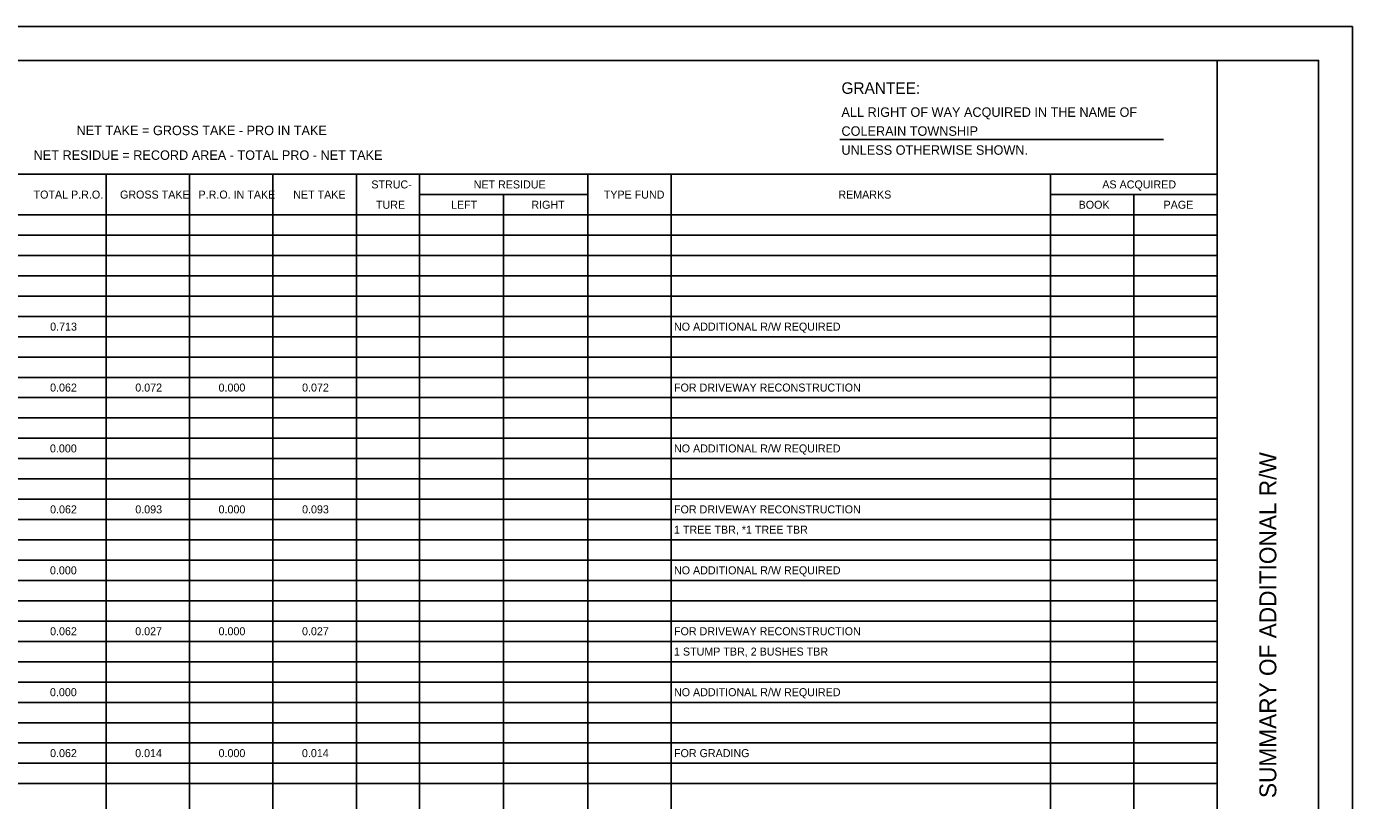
# Model space of a CAD drawing. Extents: x 0 to 34, y 0 to 22.
# Drawn here: x 14.41 to 34, y 10.57 to 22 of the extents above; entities that cross this region are included whole.
import ezdxf

# ---------------------------------------------------------------- set-up
doc = ezdxf.new("R2010")
doc.units = 0
for name, color, linetype in [('Default', 7, 'Continuous'), ('SH_Border', 7, 'Continuous'), ('SH_Cut_Line', 7, 'Continuous'), ('SH_Data', 7, 'Continuous'), ('SH_Text', 7, 'Continuous')]:
    doc.layers.add(name, color=color, linetype=linetype)

msp = doc.modelspace()

# ---------------------------------------------------------------- linework, layer by layer
at = {"layer": 'Default'}
for p, q in [((1.5, 19.818), (32, 19.818)), ((15.587, 19.818), (15.587, 3.02)), ((16.819, 19.818), (16.819, 3.02)), ((18.051, 19.818), (18.051, 3.02)), ((19.283, 19.818), (19.283, 3.02)), ((20.216, 19.818), (20.216, 3.02)), ((22.701, 19.818), (22.701, 3.02)), ((23.933, 19.818), (23.933, 3.02)), ((29.536, 19.818), (29.536, 3.02)), ((32, 19.818), (32, 3.02)), ((20.216, 19.518), (22.701, 19.518)), ((21.458, 19.518), (21.458, 3.02)), ((29.536, 19.518), (32, 19.518)), ((30.768, 19.518), (30.768, 3.02)), ((1.5, 19.218), (32, 19.218)), ((1.5, 18.918), (32, 18.918)), ((1.5, 18.618), (32, 18.618)), ((1.5, 18.318), (32, 18.318)), ((1.5, 18.018), (32, 18.018)), ((1.5, 17.718), (32, 17.718)), ((1.5, 17.418), (32, 17.418)), ((1.5, 17.119), (32, 17.119)), ((1.5, 16.819), (32, 16.819)), ((1.5, 16.519), (32, 16.519)), ((1.5, 16.219), (32, 16.219)), ((1.5, 15.919), (32, 15.919)), ((1.5, 15.619), (32, 15.619)), ((1.5, 15.319), (32, 15.319)), ((1.5, 15.019), (32, 15.019)), ((1.5, 14.719), (32, 14.719)), ((1.5, 14.419), (32, 14.419)), ((1.5, 14.119), (32, 14.119)), ((1.5, 13.819), (32, 13.819)), ((1.5, 13.519), (32, 13.519)), ((1.5, 13.219), (32, 13.219)), ((1.5, 12.919), (32, 12.919)), ((1.5, 12.619), (32, 12.619)), ((1.5, 12.319), (32, 12.319)), ((1.5, 12.019), (32, 12.019)), ((1.5, 11.719), (32, 11.719)), ((1.5, 11.419), (32, 11.419)), ((1.5, 11.119), (32, 11.119)), ((1.5, 10.819), (32, 10.819))]:
    msp.add_line(p, q, dxfattribs=at)
at = {"layer": 'SH_Border'}
msp.add_line((32, 0.5), (32, 21.5), dxfattribs=at)
msp.add_lwpolyline([(1.5, 21.5), (33.5, 21.5), (33.5, 0.5), (1.5, 0.5)], close=True, dxfattribs=at)
at = {"layer": 'SH_Cut_Line'}
msp.add_lwpolyline([(0, 0), (34, 0), (34, 22), (0, 22)], close=True, dxfattribs=at)
at = {"layer": 'SH_Text'}
msp.add_line((26.428, 20.33), (31.208, 20.33), dxfattribs=at)

# ---------------------------------------------------------------- texts
at = {"layer": 'Default'}
for s, height, p in [('STRUC-', 0.1183, (19.504, 19.609)), ('NET RESIDUE', 0.11827, (21.016, 19.609)), ('AS ACQUIRED', 0.11827, (30.304, 19.609)), ('TOTAL P.R.O.', 0.11827, (14.514, 19.459)), ('GROSS TAKE', 0.1183, (15.791, 19.459)), ('P.R.O. IN TAKE', 0.11827, (16.951, 19.459)), ('NET TAKE', 0.1183, (18.35, 19.459)), ('TURE', 0.1183, (19.573, 19.309)), ('LEFT', 0.1183, (20.682, 19.309)), ('RIGHT', 0.1183, (21.868, 19.309)), ('TYPE FUND', 0.1183, (22.938, 19.459)), ('REMARKS', 0.1183, (26.404, 19.459)), ('BOOK', 0.1183, (29.954, 19.309)), ('PAGE', 0.1183, (31.209, 19.309)), ('NO ADDITIONAL R/W REQUIRED', 0.11827, (23.976, 17.509)), ('0.713', 0.1183, (14.759, 17.509)), ('0.062', 0.1183, (14.758, 16.609)), ('0.072', 0.1183, (16.017, 16.609)), ('0.000', 0.1183, (17.247, 16.609)), ('0.072', 0.1183, (18.481, 16.609)), ('FOR DRIVEWAY RECONSTRUCTION', 0.11827, (23.976, 16.609)), ('0.000', 0.1183, (14.756, 15.71)), ('NO ADDITIONAL R/W REQUIRED', 0.11827, (23.976, 15.71)), ('0.062', 0.1183, (14.758, 14.81)), ('0.093', 0.1183, (16.017, 14.81)), ('0.000', 0.1183, (17.247, 14.81)), ('0.093', 0.1183, (18.481, 14.81)), ('FOR DRIVEWAY RECONSTRUCTION', 0.11827, (23.976, 14.81)), ('1 TREE TBR, *1 TREE TBR', 0.11827, (23.976, 14.51)), ('0.000', 0.1183, (14.756, 13.91)), ('NO ADDITIONAL R/W REQUIRED', 0.11827, (23.976, 13.91)), ('0.062', 0.1183, (14.758, 13.01)), ('0.027', 0.1183, (16.016, 13.01)), ('0.000', 0.1183, (17.247, 13.01)), ('0.027', 0.1183, (18.48, 13.01)), ('FOR DRIVEWAY RECONSTRUCTION', 0.11827, (23.976, 13.01)), ('1 STUMP TBR, 2 BUSHES TBR', 0.11827, (23.976, 12.71)), ('0.000', 0.1183, (14.756, 12.11)), ('NO ADDITIONAL R/W REQUIRED', 0.11827, (23.976, 12.11)), ('0.062', 0.1183, (14.758, 11.21)), ('0.014', 0.1183, (16.015, 11.21)), ('0.000', 0.1183, (17.247, 11.21)), ('0.014', 0.1183, (18.479, 11.21)), ('FOR GRADING', 0.11827, (23.976, 11.21))]:
    msp.add_text(s, height=height, dxfattribs=at).set_placement(p)
at = {"layer": 'SH_Data'}
msp.add_text('SUMMARY OF ADDITIONAL R/W', height=0.25, rotation=90, dxfattribs=at).set_placement((32.875, 10.606))
at = {"layer": 'SH_Text'}
for s, height, p in [('GRANTEE:', 0.17, (26.45, 21.006)), ('ALL RIGHT OF WAY ACQUIRED IN THE NAME OF', 0.14, (26.45, 20.666)), ('NET TAKE = GROSS TAKE - PRO IN TAKE', 0.14, (15.149, 20.396)), ('COLERAIN TOWNSHIP', 0.14, (26.45, 20.386)), ('UNLESS OTHERWISE SHOWN.', 0.14, (26.45, 20.106)), ('NET RESIDUE = RECORD AREA - TOTAL PRO - NET TAKE', 0.14, (14.515, 20.031))]:
    msp.add_text(s, height=height, dxfattribs=at).set_placement(p)

doc.saveas('drawing.dxf')
